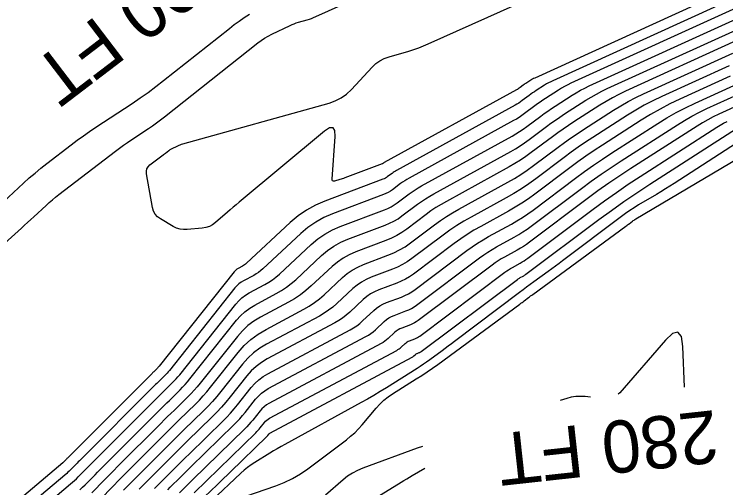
# Model space of a CAD drawing. Extents: x 1768942 to 1774819, y 723037 to 732099.
# Drawn here: x 1770403 to 1770484.7, y 726452.6 to 726507 of the extents above; entities that cross this region are included whole.
import ezdxf

# ---------------------------------------------------------------- set-up
doc = ezdxf.new("R2010")
doc.units = 0
doc.layers.add('R_Contour Annot', color=7, linetype='Continuous')
doc.layers.add('R_Contours', color=7, linetype='Continuous')

msp = doc.modelspace()

# ---------------------------------------------------------------- linework, layer by layer
at = {"layer": 'R_Contours'}
for points in [[(1770392.762, 726472.562), (1770403.774, 726482.467), (1770404.132, 726482.79), (1770404.489, 726483.115), (1770404.845, 726483.441), (1770405.2, 726483.769), (1770406.616, 726485.081), (1770406.974, 726485.405), (1770407.339, 726485.72), (1770407.711, 726486.026), (1770408.091, 726486.325), (1770414.584, 726491.305), (1770415.043, 726491.65), (1770415.507, 726491.987), (1770415.977, 726492.315), (1770416.454, 726492.635), (1770418.371, 726493.899), (1770418.846, 726494.22), (1770419.315, 726494.551), (1770419.775, 726494.892), (1770420.229, 726495.243), (1770430.956, 726503.745), (1770431.335, 726504.029), (1770431.728, 726504.29), (1770432.136, 726504.528), (1770432.557, 726504.744), (1770434.657, 726505.747), (1770434.894, 726505.854), (1770435.136, 726505.952), (1770435.381, 726506.039), (1770435.63, 726506.116), (1770436.634, 726506.405), (1770436.883, 726506.481), (1770437.129, 726506.566), (1770437.372, 726506.66), (1770437.612, 726506.763), (1770466.214, 726519.616)], [(1770488.105, 726511.248), (1770462.781, 726499.71), (1770462.663, 726499.654), (1770462.547, 726499.593), (1770462.433, 726499.529), (1770462.322, 726499.46), (1770461.859, 726499.163), (1770461.76, 726499.098), (1770461.662, 726499.031), (1770461.566, 726498.963), (1770461.471, 726498.893), (1770461.093, 726498.609), (1770460.997, 726498.54), (1770460.899, 726498.475), (1770460.799, 726498.412), (1770460.697, 726498.354), (1770445.475, 726489.99), (1770445.456, 726489.979), (1770445.437, 726489.967), (1770445.419, 726489.955), (1770445.401, 726489.942), (1770445.33, 726489.889), (1770445.312, 726489.876), (1770445.293, 726489.865), (1770445.273, 726489.855), (1770445.253, 726489.847), (1770440.957, 726488.226), (1770440.812, 726488.173), (1770440.665, 726488.124), (1770440.517, 726488.079), (1770440.368, 726488.037), (1770439.769, 726487.876), (1770439.639, 726487.86), (1770439.55, 726487.893), (1770439.5, 726487.974), (1770439.491, 726488.105), (1770439.839, 726492.986), (1770439.81, 726493.673), (1770439.598, 726494.006), (1770439.205, 726493.984), (1770438.629, 726493.607), (1770428.813, 726485.438), (1770428.471, 726485.153), (1770428.131, 726484.866), (1770427.793, 726484.577), (1770427.455, 726484.286), (1770426.091, 726483.106), (1770425.751, 726482.853), (1770425.384, 726482.661), (1770424.992, 726482.53), (1770424.573, 726482.461), (1770422.842, 726482.305), (1770422.42, 726482.299), (1770422.013, 726482.356), (1770421.621, 726482.478), (1770421.242, 726482.664), (1770419.758, 726483.536), (1770419.424, 726483.779), (1770419.163, 726484.074), (1770418.976, 726484.421), (1770418.863, 726484.818), (1770418.161, 726488.694), (1770418.142, 726488.998), (1770418.203, 726489.272), (1770418.342, 726489.515), (1770418.56, 726489.728), (1770420.062, 726490.88), (1770420.084, 726490.896), (1770420.106, 726490.912), (1770420.128, 726490.928), (1770420.151, 726490.943), (1770420.242, 726491.003), (1770420.265, 726491.019), (1770420.287, 726491.034), (1770420.309, 726491.051), (1770420.331, 726491.067), (1770420.729, 726491.384), (1770420.805, 726491.44), (1770420.882, 726491.491), (1770420.963, 726491.539), (1770421.046, 726491.581), (1770421.75, 726491.917), (1770421.897, 726491.984), (1770422.046, 726492.043), (1770422.198, 726492.097), (1770422.352, 726492.143), (1770439.137, 726496.832), (1770439.862, 726497.087), (1770440.532, 726497.433), (1770441.147, 726497.87), (1770441.707, 726498.397), (1770444.093, 726500.963), (1770444.518, 726501.364), (1770444.984, 726501.696), (1770445.491, 726501.962), (1770446.041, 726502.159), (1770448.32, 726502.814), (1770448.886, 726502.988), (1770449.445, 726503.181), (1770449.997, 726503.394), (1770450.541, 726503.627), (1770460.647, 726508.169)], [(1770487.68, 726509.801), (1770464.867, 726499.407), (1770464.621, 726499.289), (1770464.38, 726499.163), (1770464.143, 726499.029), (1770463.911, 726498.885), (1770462.947, 726498.266), (1770462.741, 726498.132), (1770462.538, 726497.993), (1770462.337, 726497.851), (1770462.139, 726497.705), (1770461.352, 726497.115), (1770461.153, 726496.971), (1770460.95, 726496.834), (1770460.741, 726496.705), (1770460.528, 726496.583), (1770446.905, 726489.098), (1770446.77, 726489.02), (1770446.637, 726488.938), (1770446.507, 726488.851), (1770446.38, 726488.759), (1770445.879, 726488.384), (1770445.751, 726488.295), (1770445.618, 726488.215), (1770445.48, 726488.146), (1770445.336, 726488.086), (1770438.666, 726485.57), (1770437.58, 726485.1), (1770436.555, 726484.532), (1770435.591, 726483.865), (1770434.688, 726483.101), (1770429.666, 726478.422), (1770429.556, 726478.326), (1770429.441, 726478.238), (1770429.32, 726478.157), (1770429.194, 726478.085), (1770428.678, 726477.809), (1770428.554, 726477.735), (1770428.44, 726477.649), (1770428.334, 726477.552), (1770428.239, 726477.443), (1770419.605, 726466.584), (1770419.544, 726466.51), (1770419.48, 726466.437), (1770419.415, 726466.367), (1770419.347, 726466.299), (1770419.071, 726466.029), (1770419.002, 726465.962), (1770418.934, 726465.894), (1770418.865, 726465.827), (1770418.797, 726465.759), (1770409.181, 726456.136), (1770409.127, 726456.082), (1770409.073, 726456.028), (1770409.019, 726455.973), (1770408.966, 726455.919), (1770408.751, 726455.701), (1770408.697, 726455.647), (1770408.642, 726455.595), (1770408.585, 726455.544), (1770408.527, 726455.494), (1770398.053, 726446.657)], [(1770487.256, 726508.353), (1770466.953, 726499.103), (1770466.579, 726498.925), (1770466.212, 726498.733), (1770465.852, 726498.528), (1770465.5, 726498.311), (1770464.035, 726497.37), (1770463.722, 726497.166), (1770463.414, 726496.955), (1770463.109, 726496.739), (1770462.808, 726496.518), (1770461.612, 726495.62), (1770461.309, 726495.401), (1770461, 726495.194), (1770460.683, 726494.997), (1770460.359, 726494.812), (1770448.335, 726488.205), (1770448.083, 726488.061), (1770447.836, 726487.908), (1770447.595, 726487.746), (1770447.36, 726487.576), (1770446.428, 726486.878), (1770446.191, 726486.713), (1770445.943, 726486.566), (1770445.686, 726486.436), (1770445.418, 726486.324), (1770439.55, 726484.111), (1770438.55, 726483.678), (1770437.607, 726483.155), (1770436.719, 726482.541), (1770435.887, 726481.838), (1770431.547, 726477.794), (1770431.3, 726477.578), (1770431.04, 726477.379), (1770430.768, 726477.198), (1770430.484, 726477.034), (1770429.322, 726476.414), (1770429.043, 726476.246), (1770428.784, 726476.053), (1770428.547, 726475.833), (1770428.331, 726475.589), (1770420.789, 726466.102), (1770420.657, 726465.942), (1770420.522, 726465.787), (1770420.381, 726465.636), (1770420.235, 726465.489), (1770419.643, 726464.911), (1770419.495, 726464.766), (1770419.348, 726464.621), (1770419.201, 726464.476), (1770419.054, 726464.33), (1770410.587, 726455.856), (1770410.454, 726455.723), (1770410.322, 726455.59), (1770410.191, 726455.457), (1770410.059, 726455.324), (1770409.533, 726454.79), (1770409.401, 726454.658), (1770409.265, 726454.53), (1770409.126, 726454.404), (1770408.984, 726454.282), (1770399.784, 726446.52)], [(1770400.546, 726484.402), (1770404.038, 726487.638), (1770404.687, 726488.225), (1770405.35, 726488.797), (1770406.025, 726489.354), (1770406.714, 726489.895), (1770409.495, 726492.028), (1770410.194, 726492.555), (1770410.903, 726493.069), (1770411.621, 726493.57), (1770412.348, 726494.059), (1770416.5, 726496.794), (1770417.428, 726497.42), (1770418.342, 726498.067), (1770419.242, 726498.733), (1770420.127, 726499.419), (1770427.697, 726505.419), (1770428.254, 726505.848), (1770428.821, 726506.262), (1770429.4, 726506.66), (1770429.989, 726507.043)], [(1770401.516, 726446.383), (1770409.441, 726453.07), (1770409.667, 726453.265), (1770409.888, 726453.464), (1770410.104, 726453.669), (1770410.315, 726453.879), (1770411.152, 726454.729), (1770411.362, 726454.941), (1770411.571, 726455.153), (1770411.782, 726455.365), (1770411.992, 726455.576), (1770419.312, 726462.901), (1770419.536, 726463.125), (1770419.762, 726463.348), (1770419.988, 726463.571), (1770420.215, 726463.793), (1770421.123, 726464.679), (1770421.347, 726464.904), (1770421.563, 726465.136), (1770421.771, 726465.374), (1770421.972, 726465.619), (1770428.424, 726473.734), (1770428.76, 726474.115), (1770429.129, 726474.456), (1770429.531, 726474.758), (1770429.966, 726475.019), (1770431.774, 726475.984), (1770432.217, 726476.239), (1770432.64, 726476.521), (1770433.044, 726476.83), (1770433.428, 726477.165), (1770437.086, 726480.574), (1770437.847, 726481.218), (1770438.658, 726481.778), (1770439.521, 726482.256), (1770440.435, 726482.652), (1770445.501, 726484.563), (1770445.892, 726484.726), (1770446.268, 726484.916), (1770446.63, 726485.131), (1770446.977, 726485.373), (1770448.339, 726486.393), (1770448.683, 726486.642), (1770449.036, 726486.878), (1770449.396, 726487.101), (1770449.765, 726487.312), (1770460.19, 726493.04), (1770460.625, 726493.289), (1770461.05, 726493.553), (1770461.465, 726493.832), (1770461.871, 726494.126), (1770463.476, 726495.33), (1770463.88, 726495.627), (1770464.289, 726495.917), (1770464.703, 726496.199), (1770465.123, 726496.474), (1770467.089, 726497.736), (1770467.562, 726498.028), (1770468.045, 726498.303), (1770468.537, 726498.56), (1770469.039, 726498.799), (1770486.831, 726506.906)], [(1770410.511, 726452.399), (1770410.807, 726452.68), (1770411.098, 726452.968), (1770412.246, 726454.134), (1770412.533, 726454.426), (1770412.821, 726454.716), (1770413.109, 726455.006), (1770413.398, 726455.296), (1770419.569, 726461.472), (1770419.872, 726461.774), (1770420.176, 726462.075), (1770420.481, 726462.375), (1770420.786, 726462.674), (1770422.011, 726463.87), (1770422.312, 726464.173), (1770422.604, 726464.485), (1770422.885, 726464.807), (1770423.156, 726465.137), (1770428.517, 726471.88), (1770428.973, 726472.397), (1770429.473, 726472.86), (1770430.019, 726473.269), (1770430.61, 726473.624), (1770433.065, 726474.934), (1770433.665, 726475.28), (1770434.239, 726475.662), (1770434.788, 726476.082), (1770435.309, 726476.537), (1770438.286, 726479.311), (1770438.975, 726479.894), (1770439.71, 726480.402), (1770440.492, 726480.835), (1770441.32, 726481.193), (1770445.584, 726482.802), (1770446.098, 726483.017), (1770446.593, 726483.266), (1770447.069, 726483.55), (1770447.527, 726483.868), (1770449.318, 726485.21), (1770449.771, 726485.537), (1770450.235, 726485.848), (1770450.71, 726486.142), (1770451.195, 726486.42), (1770460.021, 726491.269), (1770460.566, 726491.582), (1770461.1, 726491.913), (1770461.622, 726492.263), (1770462.131, 726492.631), (1770464.145, 726494.142), (1770464.651, 726494.515), (1770465.165, 726494.879), (1770465.685, 726495.233), (1770466.211, 726495.578), (1770468.678, 726497.162), (1770469.271, 726497.528), (1770469.877, 726497.873), (1770470.495, 726498.195), (1770471.124, 726498.496), (1770486.407, 726505.458)], [(1770485.982, 726504.011), (1770473.21, 726498.192), (1770472.453, 726497.83), (1770471.71, 726497.442), (1770470.981, 726497.028), (1770470.267, 726496.587), (1770467.299, 726494.682), (1770466.666, 726494.267), (1770466.04, 726493.841), (1770465.423, 726493.403), (1770464.813, 726492.954), (1770462.391, 726491.136), (1770461.778, 726490.693), (1770461.15, 726490.272), (1770460.508, 726489.874), (1770459.852, 726489.498), (1770452.625, 726485.527), (1770452.023, 726485.183), (1770451.435, 726484.818), (1770450.86, 726484.433), (1770450.298, 726484.027), (1770448.076, 726482.363), (1770447.509, 726481.968), (1770446.918, 726481.616), (1770446.304, 726481.307), (1770445.666, 726481.041), (1770442.204, 726479.735), (1770441.462, 726479.413), (1770440.761, 726479.025), (1770440.102, 726478.57), (1770439.485, 726478.047), (1770437.098, 726475.823), (1770436.486, 726475.289), (1770435.844, 726474.797), (1770435.17, 726474.349), (1770434.466, 726473.943), (1770431.254, 726472.229), (1770430.508, 726471.78), (1770429.818, 726471.264), (1770429.186, 726470.679), (1770428.61, 726470.025), (1770424.34, 726464.655), (1770423.999, 726464.239), (1770423.645, 726463.835), (1770423.278, 726463.442), (1770422.899, 726463.06), (1770421.358, 726461.556), (1770420.973, 726461.18), (1770420.59, 726460.802), (1770420.208, 726460.423), (1770419.826, 726460.043), (1770414.803, 726455.016), (1770414.436, 726454.648), (1770414.07, 726454.279), (1770413.704, 726453.91), (1770413.339, 726453.539), (1770411.88, 726452.057)], [(1770412.662, 726451.146), (1770414.432, 726452.945), (1770414.875, 726453.394), (1770415.319, 726453.842), (1770415.764, 726454.289), (1770416.209, 726454.736), (1770420.084, 726458.614), (1770420.543, 726459.072), (1770421.004, 726459.529), (1770421.466, 726459.984), (1770421.93, 726460.438), (1770423.787, 726462.25), (1770424.244, 726462.71), (1770424.686, 726463.184), (1770425.112, 726463.671), (1770425.524, 726464.172), (1770428.703, 726468.171), (1770429.398, 726468.961), (1770430.163, 726469.668), (1770430.996, 726470.292), (1770431.898, 726470.833), (1770436.246, 726473.154), (1770436.868, 726473.513), (1770437.464, 726473.91), (1770438.032, 726474.344), (1770438.574, 726474.817), (1770440.684, 726476.784), (1770441.23, 726477.246), (1770441.813, 726477.648), (1770442.433, 726477.992), (1770443.089, 726478.276), (1770445.909, 726479.34), (1770446.592, 726479.625), (1770447.249, 726479.956), (1770447.881, 726480.332), (1770448.488, 726480.755), (1770451.277, 726482.844), (1770451.948, 726483.328), (1770452.634, 726483.788), (1770453.337, 726484.223), (1770454.055, 726484.635), (1770459.683, 726487.727), (1770460.45, 726488.166), (1770461.2, 726488.632), (1770461.934, 726489.124), (1770462.65, 726489.642), (1770465.482, 726491.767), (1770466.194, 726492.291), (1770466.916, 726492.803), (1770467.647, 726493.301), (1770468.387, 726493.785), (1770471.856, 726496.013), (1770472.69, 726496.528), (1770473.542, 726497.012), (1770474.411, 726497.466), (1770475.296, 726497.888), (1770485.558, 726502.564)], [(1770485.133, 726501.116), (1770477.382, 726497.584), (1770476.368, 726497.101), (1770475.375, 726496.582), (1770474.4, 726496.028), (1770473.445, 726495.438), (1770469.475, 726492.889), (1770468.628, 726492.334), (1770467.791, 726491.764), (1770466.965, 726491.179), (1770466.15, 726490.579), (1770462.91, 726488.147), (1770462.09, 726487.554), (1770461.251, 726486.992), (1770460.392, 726486.459), (1770459.514, 726485.956), (1770455.485, 726483.742), (1770454.65, 726483.264), (1770453.834, 726482.758), (1770453.036, 726482.223), (1770452.256, 726481.661), (1770448.667, 726478.972), (1770448.139, 726478.605), (1770447.589, 726478.277), (1770447.018, 726477.99), (1770446.425, 726477.742), (1770443.974, 726476.817), (1770443.403, 726476.57), (1770442.865, 726476.272), (1770442.358, 726475.922), (1770441.883, 726475.52), (1770440.049, 726473.811), (1770439.578, 726473.4), (1770439.084, 726473.022), (1770438.567, 726472.677), (1770438.026, 726472.366), (1770431.97, 726469.133), (1770431.187, 726468.663), (1770430.465, 726468.122), (1770429.803, 726467.509), (1770429.2, 726466.824), (1770426.707, 726463.69), (1770426.226, 726463.104), (1770425.727, 726462.533), (1770425.21, 726461.979), (1770424.675, 726461.441), (1770422.502, 726459.319), (1770421.959, 726458.788), (1770421.418, 726458.255), (1770420.879, 726457.721), (1770420.341, 726457.185), (1770417.615, 726454.456), (1770417.091, 726453.931), (1770416.568, 726453.405), (1770416.046, 726452.878), (1770415.525, 726452.35)], [(1770485.258, 726499.919), (1770479.467, 726497.281), (1770478.326, 726496.736), (1770477.207, 726496.152), (1770476.109, 726495.527), (1770475.034, 726494.864), (1770470.563, 726491.993), (1770469.609, 726491.368), (1770468.667, 726490.726), (1770467.737, 726490.067), (1770466.818, 726489.391), (1770462.794, 726486.371), (1770462.06, 726485.841), (1770461.31, 726485.337), (1770460.542, 726484.861), (1770459.756, 726484.411), (1770456.58, 726482.665), (1770455.794, 726482.216), (1770455.026, 726481.739), (1770454.275, 726481.236), (1770453.541, 726480.706), (1770448.845, 726477.189), (1770448.397, 726476.877), (1770447.93, 726476.599), (1770447.445, 726476.355), (1770446.941, 726476.144), (1770444.858, 726475.359), (1770444.374, 726475.149), (1770443.916, 726474.895), (1770443.486, 726474.598), (1770443.083, 726474.257), (1770441.524, 726472.804), (1770441.124, 726472.455), (1770440.705, 726472.134), (1770440.265, 726471.842), (1770439.805, 726471.577), (1770432.033, 726467.428), (1770431.375, 726467.033), (1770430.767, 726466.577), (1770430.209, 726466.061), (1770429.702, 726465.485), (1770427.773, 726463.059), (1770427.282, 726462.461), (1770426.772, 726461.879), (1770426.245, 726461.313), (1770425.699, 726460.764), (1770422.844, 726457.977), (1770422.337, 726457.481), (1770421.831, 726456.983), (1770421.327, 726456.483), (1770420.825, 726455.982), (1770418.818, 726453.974), (1770418.317, 726453.471), (1770417.817, 726452.968), (1770417.317, 726452.464)], [(1770419.065, 726452.532), (1770419.461, 726452.93), (1770419.858, 726453.328), (1770421.447, 726454.918), (1770421.845, 726455.315), (1770422.244, 726455.711), (1770422.645, 726456.105), (1770423.046, 726456.498), (1770426.954, 726460.312), (1770427.397, 726460.758), (1770427.825, 726461.217), (1770428.239, 726461.69), (1770428.638, 726462.175), (1770430.204, 726464.145), (1770430.616, 726464.613), (1770431.069, 726465.032), (1770431.563, 726465.402), (1770432.097, 726465.723), (1770441.585, 726470.788), (1770441.963, 726471.006), (1770442.325, 726471.247), (1770442.67, 726471.511), (1770442.999, 726471.798), (1770444.282, 726472.993), (1770444.614, 726473.274), (1770444.968, 726473.519), (1770445.344, 726473.727), (1770445.743, 726473.9), (1770447.457, 726474.546), (1770447.871, 726474.719), (1770448.271, 726474.92), (1770448.655, 726475.149), (1770449.024, 726475.406), (1770454.996, 726479.879), (1770455.598, 726480.314), (1770456.214, 726480.727), (1770456.845, 726481.118), (1770457.489, 726481.487), (1770460.096, 726482.919), (1770460.741, 726483.288), (1770461.371, 726483.68), (1770461.987, 726484.093), (1770462.589, 726484.528), (1770467.487, 726488.204), (1770468.508, 726488.955), (1770469.542, 726489.688), (1770470.59, 726490.402), (1770471.651, 726491.097), (1770476.928, 726494.485), (1770477.97, 726495.128), (1770479.033, 726495.733), (1770480.117, 726496.299), (1770481.223, 726496.826), (1770485.685, 726498.86)], [(1770420.606, 726452.389), (1770420.898, 726452.682), (1770422.07, 726453.855), (1770422.363, 726454.147), (1770422.657, 726454.439), (1770422.952, 726454.73), (1770423.248, 726455.019), (1770428.209, 726459.86), (1770428.549, 726460.203), (1770428.879, 726460.556), (1770429.196, 726460.919), (1770429.503, 726461.292), (1770430.706, 726462.806), (1770431.023, 726463.165), (1770431.371, 726463.487), (1770431.75, 726463.771), (1770432.161, 726464.018), (1770443.365, 726469.999), (1770443.662, 726470.17), (1770443.946, 726470.359), (1770444.217, 726470.566), (1770444.475, 726470.792), (1770445.481, 726471.73), (1770445.741, 726471.95), (1770446.019, 726472.142), (1770446.315, 726472.306), (1770446.628, 726472.441), (1770447.973, 726472.948), (1770448.298, 726473.084), (1770448.611, 726473.242), (1770448.913, 726473.422), (1770449.202, 726473.623), (1770456.45, 726479.052), (1770456.921, 726479.392), (1770457.402, 726479.715), (1770457.895, 726480.02), (1770458.399, 726480.308), (1770460.436, 726481.428), (1770460.94, 726481.716), (1770461.432, 726482.022), (1770461.914, 726482.345), (1770462.384, 726482.685), (1770468.155, 726487.016), (1770469.279, 726487.843), (1770470.418, 726488.65), (1770471.571, 726489.436), (1770472.739, 726490.201), (1770479.187, 726494.341), (1770480.011, 726494.85), (1770480.852, 726495.328), (1770481.71, 726495.775), (1770482.584, 726496.193), (1770486.113, 726497.8)], [(1770486.54, 726496.741), (1770483.944, 726495.559), (1770483.302, 726495.252), (1770482.671, 726494.922), (1770482.053, 726494.571), (1770481.446, 726494.197), (1770473.827, 726489.304), (1770472.552, 726488.47), (1770471.294, 726487.612), (1770470.051, 726486.731), (1770468.824, 726485.828), (1770462.179, 726480.842), (1770461.84, 726480.597), (1770461.494, 726480.364), (1770461.139, 726480.144), (1770460.776, 726479.936), (1770459.308, 726479.13), (1770458.945, 726478.922), (1770458.591, 726478.702), (1770458.244, 726478.47), (1770457.905, 726478.225), (1770449.381, 726471.84), (1770449.171, 726471.694), (1770448.952, 726471.564), (1770448.725, 726471.449), (1770448.488, 726471.351), (1770447.513, 726470.982), (1770447.285, 726470.884), (1770447.071, 726470.765), (1770446.869, 726470.626), (1770446.68, 726470.466), (1770445.95, 726469.785), (1770445.763, 726469.622), (1770445.566, 726469.471), (1770445.36, 726469.334), (1770445.144, 726469.21), (1770432.225, 726462.313), (1770431.938, 726462.141), (1770431.673, 726461.942), (1770431.43, 726461.717), (1770431.208, 726461.466), (1770430.368, 726460.409), (1770430.154, 726460.148), (1770429.932, 726459.894), (1770429.702, 726459.648), (1770429.464, 726459.408), (1770423.451, 726453.54), (1770423.26, 726453.354), (1770423.07, 726453.167), (1770422.881, 726452.979), (1770422.692, 726452.791), (1770421.938, 726452.036)], [(1770423.653, 726452.061), (1770430.719, 726458.956), (1770430.854, 726459.092), (1770430.985, 726459.233), (1770431.111, 726459.377), (1770431.233, 726459.525), (1770431.711, 726460.126), (1770431.836, 726460.269), (1770431.975, 726460.397), (1770432.125, 726460.51), (1770432.288, 726460.608), (1770446.924, 726468.421), (1770447.058, 726468.498), (1770447.186, 726468.584), (1770447.309, 726468.677), (1770447.425, 726468.779), (1770447.879, 726469.202), (1770447.997, 726469.302), (1770448.123, 726469.389), (1770448.256, 726469.463), (1770448.397, 726469.524), (1770449.004, 726469.753), (1770449.151, 726469.814), (1770449.293, 726469.885), (1770449.429, 726469.966), (1770449.559, 726470.057), (1770459.359, 726477.398), (1770459.566, 726477.548), (1770459.779, 726477.69), (1770459.996, 726477.824), (1770460.218, 726477.951), (1770461.116, 726478.445), (1770461.338, 726478.572), (1770461.555, 726478.707), (1770461.767, 726478.849), (1770461.974, 726478.999), (1770469.492, 726484.64), (1770470.822, 726485.619), (1770472.169, 726486.574), (1770473.533, 726487.503), (1770474.915, 726488.408), (1770483.706, 726494.052), (1770484.094, 726494.292), (1770484.49, 726494.517), (1770484.894, 726494.728)], [(1770424.108, 726450.905), (1770426.293, 726452.982), (1770426.68, 726453.35), (1770427.066, 726453.72), (1770427.45, 726454.092), (1770427.833, 726454.464), (1770431.973, 726458.504), (1770432.006, 726458.537), (1770432.038, 726458.571), (1770432.068, 726458.606), (1770432.097, 726458.642), (1770432.213, 726458.787), (1770432.243, 726458.821), (1770432.276, 726458.852), (1770432.313, 726458.879), (1770432.352, 726458.903), (1770448.704, 726467.632), (1770448.756, 726467.663), (1770448.807, 726467.696), (1770448.855, 726467.733), (1770448.9, 726467.773), (1770449.079, 726467.939), (1770449.125, 726467.978), (1770449.174, 726468.012), (1770449.226, 726468.041), (1770449.282, 726468.065), (1770449.52, 726468.155), (1770449.578, 726468.179), (1770449.633, 726468.207), (1770449.687, 726468.239), (1770449.738, 726468.274), (1770460.814, 726476.571), (1770460.889, 726476.625), (1770460.967, 726476.677), (1770461.046, 726476.727), (1770461.127, 726476.773), (1770461.456, 726476.953), (1770461.537, 726477), (1770461.616, 726477.049), (1770461.694, 726477.101), (1770461.769, 726477.156), (1770470.161, 726483.453), (1770471.593, 726484.507), (1770473.045, 726485.536), (1770474.514, 726486.537), (1770476.003, 726487.512), (1770485.965, 726493.908)], [(1770487.263, 726493.079), (1770478.809, 726487.603), (1770478.307, 726487.281), (1770477.801, 726486.964), (1770477.292, 726486.651), (1770476.78, 726486.344), (1770474.727, 726485.124), (1770474.218, 726484.813), (1770473.718, 726484.488), (1770473.227, 726484.149), (1770472.746, 726483.797), (1770465.987, 726478.718), (1770465.576, 726478.41), (1770465.164, 726478.103), (1770464.751, 726477.797), (1770464.336, 726477.492), (1770462.679, 726476.277), (1770462.265, 726475.972), (1770461.852, 726475.666), (1770461.439, 726475.359), (1770461.028, 726475.051), (1770453.558, 726469.431), (1770453.205, 726469.166), (1770452.851, 726468.902), (1770452.496, 726468.639), (1770452.14, 726468.377), (1770450.716, 726467.332), (1770450.358, 726467.074), (1770449.995, 726466.822), (1770449.628, 726466.577), (1770449.257, 726466.339), (1770445.739, 726464.121), (1770445.025, 726463.679), (1770444.304, 726463.247), (1770443.577, 726462.827), (1770442.843, 726462.418), (1770434.068, 726457.616), (1770433.626, 726457.37), (1770433.187, 726457.119), (1770432.751, 726456.862), (1770432.319, 726456.599), (1770430.597, 726455.536), (1770430.174, 726455.26), (1770429.768, 726454.963), (1770429.377, 726454.646), (1770429.002, 726454.308), (1770425.606, 726451.08)], [(1770427.358, 726450.913), (1770433.023, 726452.857), (1770434.001, 726453.236), (1770434.941, 726453.688), (1770435.842, 726454.213), (1770436.704, 726454.811), (1770441.134, 726458.148), (1770441.624, 726458.54), (1770442.091, 726458.956), (1770442.533, 726459.399), (1770442.952, 726459.866), (1770444.577, 726461.788), (1770444.999, 726462.25), (1770445.452, 726462.676), (1770445.937, 726463.066), (1770446.454, 726463.419), (1770449.169, 726465.131), (1770449.796, 726465.534), (1770450.414, 726465.947), (1770451.026, 726466.371), (1770451.63, 726466.806), (1770461.074, 726473.735), (1770461.199, 726473.827), (1770461.324, 726473.92), (1770461.449, 726474.012), (1770461.573, 726474.106), (1770462.069, 726474.479), (1770462.193, 726474.572), (1770462.318, 726474.665), (1770462.443, 726474.757), (1770462.568, 726474.849), (1770473.263, 726482.692), (1770473.358, 726482.762), (1770473.453, 726482.832), (1770473.548, 726482.903), (1770473.642, 726482.974), (1770474.019, 726483.257), (1770474.115, 726483.327), (1770474.212, 726483.394), (1770474.31, 726483.458), (1770474.411, 726483.519), (1770486.249, 726490.55)], [(1770480.014, 726464.206), (1770479.815, 726468.875), (1770479.643, 726470.001), (1770479.25, 726470.493), (1770478.636, 726470.352), (1770477.801, 726469.577), (1770472.558, 726463.524), (1770472.395, 726463.372)], [(1770469.197, 726463.023), (1770468.59, 726463.097), (1770468.05, 726463.134), (1770467.517, 726463.112), (1770466.989, 726463.032), (1770466.466, 726462.892), (1770465.691, 726462.639)], [(1770449.868, 726457.367), (1770449.289, 726457.17), (1770443.016, 726454.875), (1770442.406, 726454.62), (1770441.828, 726454.312), (1770441.28, 726453.952), (1770440.764, 726453.54), (1770438.739, 726451.767)], [(1770440.358, 726448.916), (1770447.428, 726453.264), (1770447.748, 726453.46), (1770448.069, 726453.655), (1770448.39, 726453.849), (1770448.712, 726454.041), (1770450.139, 726454.889)]]:
    msp.add_lwpolyline(points, dxfattribs=at)

# ---------------------------------------------------------------- texts
at = {"layer": 'R_Contour Annot'}
for s, rotation, p in [('290 FT', 217.3314, (1770424.842, 726516.459)), ('280 FT', 186.24124, (1770483.508, 726461.57))]:
    msp.add_text(s, height=6, rotation=rotation, dxfattribs=at).set_placement(p)

doc.saveas('drawing.dxf')
